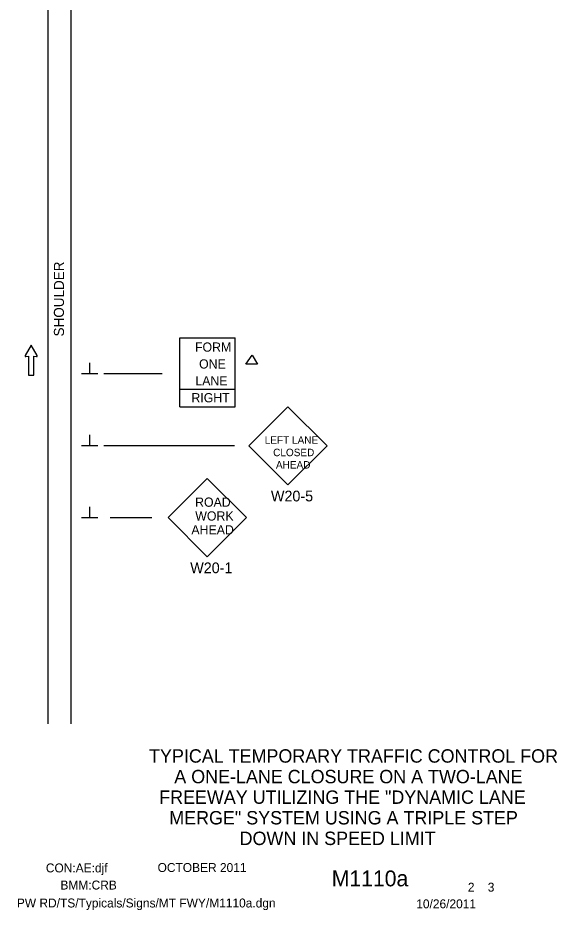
# Model space of a CAD drawing. Extents: x 15261 to 18126, y 1908 to 6555.
# Drawn here: x 16620 to 16994, y 2176 to 2796 of the extents above; entities that cross this region are included whole.
import ezdxf

# ---------------------------------------------------------------- set-up
doc = ezdxf.new("R2010")
doc.units = 0
for name, color, linetype in [('BORDER_SIGNAL_WO', 7, 'Continuous'), ('MT_SCRATCH_LEVEL_E', 7, 'Continuous'), ('PAVT_EDGE_EX', 7, 'Continuous'), ('TRAFFIC_SIGNS_PR', 7, 'Continuous'), ('TYPICAL_TEXT_DIMEN_PR', 7, 'Continuous')]:
    doc.layers.add(name, color=color, linetype=linetype)

msp = doc.modelspace()

# ---------------------------------------------------------------- linework, layer by layer
at = {"layer": 'MT_SCRATCH_LEVEL_E'}
for p, q in [((16628.88, 2568.38), (16624.77, 2561.14)), ((16633.03, 2561.14), (16628.88, 2568.38)), ((16625.25, 2560.45), (16627.03, 2560.77)), ((16627.03, 2560.77), (16627.03, 2547.51)), ((16630.77, 2547.51), (16630.77, 2560.77)), ((16630.77, 2560.77), (16632.55, 2560.45)), ((16627.03, 2547.51), (16630.77, 2547.51))]:
    msp.add_line(p, q, dxfattribs=at)
for centre, start, end in [((16625.17, 2560.91), 150.42484, 279.96381), ((16632.62, 2560.91), 260.03619, 29.77312)]:
    msp.add_arc(centre, 0.463, start, end, dxfattribs=at)
at = {"layer": 'PAVT_EDGE_EX'}
for p, q in [((16640.35, 3138.78), (16640.35, 2305.55)), ((16656.35, 3138.78), (16656.35, 2305.55))]:
    msp.add_line(p, q, dxfattribs=at)
at = {"layer": 'TRAFFIC_SIGNS_PR'}
for p, q in [((16732.11, 2525.54), (16732.11, 2573.5)), ((16732.11, 2573.5), (16770.47, 2573.5)), ((16770.47, 2525.54), (16770.47, 2573.5)), ((16732.11, 2537.95), (16770.47, 2537.95)), ((16732.11, 2525.54), (16770.47, 2525.54)), ((16807.18, 2525.7), (16780.03, 2498.55)), ((16834.33, 2498.55), (16807.18, 2525.7)), ((16780.03, 2498.55), (16807.18, 2471.4)), ((16807.18, 2471.4), (16834.33, 2498.55)), ((16751.15, 2475.85), (16724, 2448.69)), ((16778.3, 2448.69), (16751.15, 2475.85)), ((16724, 2448.69), (16751.15, 2421.54)), ((16751.15, 2421.54), (16778.3, 2448.69))]:
    msp.add_line(p, q, dxfattribs=at)
at = {"layer": 'TYPICAL_TEXT_DIMEN_PR'}
for p, q in [((16669.48, 2548.48), (16669.48, 2556.26)), ((16675.1, 2548.48), (16663.85, 2548.48)), ((16719.76, 2548.48), (16679.35, 2548.48)), ((16669.48, 2498.48), (16669.48, 2506.26)), ((16675.1, 2498.48), (16663.85, 2498.48)), ((16770.05, 2498.48), (16679.35, 2498.48)), ((16669.48, 2448.48), (16669.48, 2456.26)), ((16675.1, 2448.48), (16663.85, 2448.48)), ((16712.55, 2448.48), (16683.78, 2448.48))]:
    msp.add_line(p, q, dxfattribs=at)
msp.add_lwpolyline([(16777.98, 2555.15), (16782.35, 2561.45), (16786.05, 2555.15)], close=True, dxfattribs=at)

# ---------------------------------------------------------------- texts
at = {"layer": 'BORDER_SIGNAL_WO'}
for s, height, p in [('TYPICAL TEMPORARY TRAFFIC CONTROL FOR', 9.3, (16710.73, 2278.54)), ('A ONE-LANE CLOSURE ON A TWO-LANE', 9.3, (16728.24, 2264.24)), ('FREEWAY UTILIZING THE "DYNAMIC LANE', 9.3, (16717.74, 2249.94)), ('MERGE" SYSTEM USING A TRIPLE STEP', 9.3, (16724.73, 2235.64)), ('DOWN IN SPEED LIMIT', 9.3, (16773.6, 2221.34)), ('CON:AE:djf  ', 6.2, (16639.05, 2202.35)), ('    OCTOBER 2011    ', 6.2, (16707.44, 2202.63)), ('    M1110a   ', 11, (16821.22, 2192.67)), ('BMM:CRB   ', 6.2, (16649.17, 2190.46)), (' 2    3 ', 6.2, (16929.81, 2188.99)), ('PW RD/TS/Typicals/Signs/MT FWY/M1110a.dgn      ', 6.2, (16618.92, 2178)), ('10/26/2011    ', 6.2, (16896.29, 2177.42))]:
    msp.add_text(s, height=height, dxfattribs=at).set_placement(p)
at = {"layer": 'TRAFFIC_SIGNS_PR'}
for s, height, p in [('FORM', 6.394, (16742.64, 2563.91)), ('ONE', 6.394, (16745.45, 2552.19)), ('LANE', 6.394, (16742.87, 2540.47)), ('RIGHT', 6.394, (16740.15, 2528.74)), ('LEFT LANE', 5.2, (16791.06, 2499.94)), ('CLOSED', 5.2, (16796.89, 2491.34)), ('AHEAD', 5.2, (16798.84, 2482.74)), ('W20-5', 7.44, (16795.36, 2459.96)), ('ROAD', 6.4, (16742.69, 2456.23)), ('WORK', 6.4, (16742.8, 2446.63)), ('AHEAD', 6.4, (16740.11, 2437.03)), ('W20-1', 7.44, (16739.32, 2410.1))]:
    msp.add_text(s, height=height, dxfattribs=at).set_placement(p)
at = {"layer": 'TYPICAL_TEXT_DIMEN_PR'}
msp.add_text('SHOULDER', height=7, rotation=90, dxfattribs=at).set_placement((16651.63, 2574.49))

doc.saveas('drawing.dxf')
